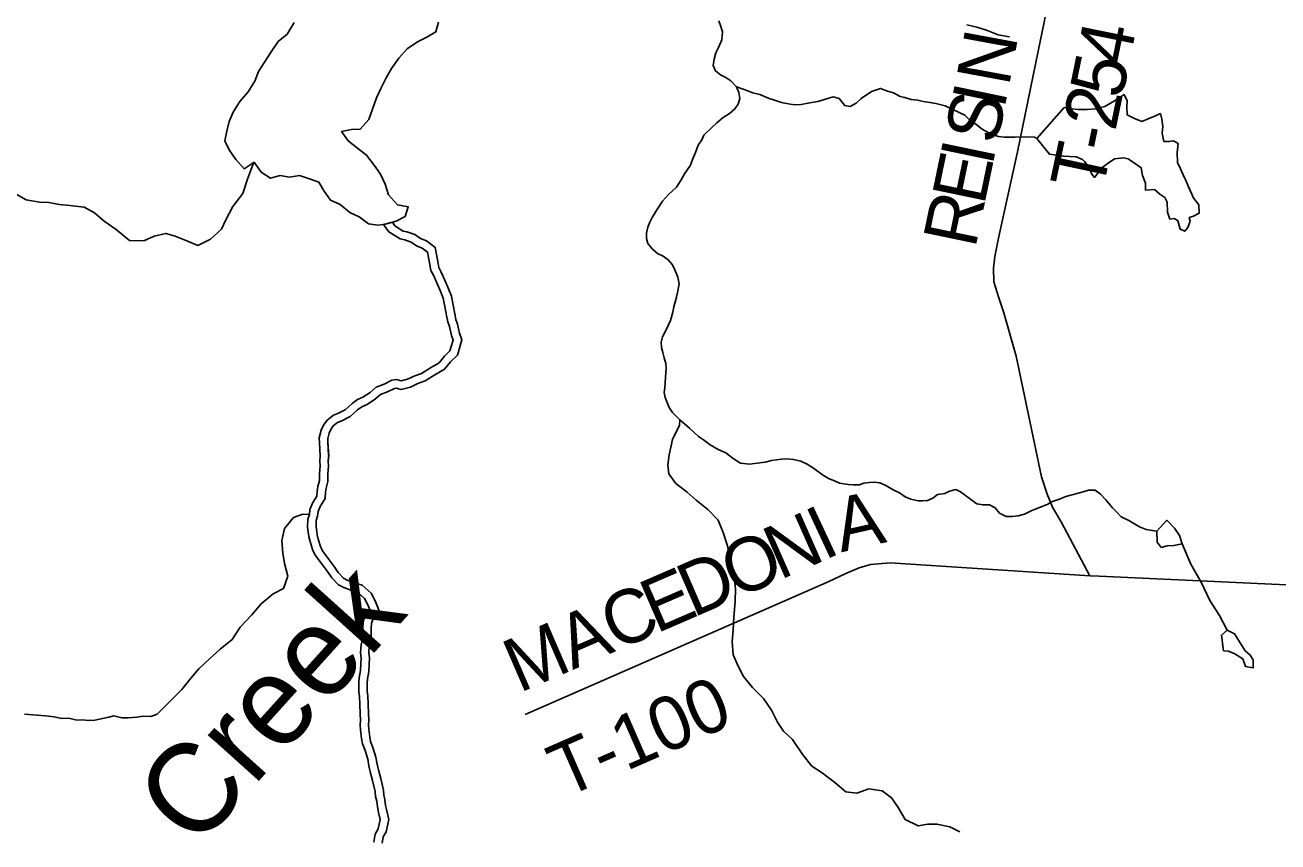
# Model space of a CAD drawing. Extents: x 1310247 to 1664935, y 235267 to 584339.
# Drawn here: x 1510976 to 1517993, y 362419 to 366994 of the extents above; entities that cross this region are included whole.
import ezdxf

# ---------------------------------------------------------------- set-up
doc = ezdxf.new("R2010")
doc.units = 0
for name, color, linetype in [('GM_X_Major_Lake', 7, 'Continuous'), ('GM_X_Minor_Lake', 7, 'Continuous'), ('GM_X_Minor_River', 7, 'Continuous'), ('GM_X_Minor_River_Text', 7, 'Continuous'), ('GM_X_Township_Road', 7, 'Continuous'), ('GM_X_Township_Road_Text', 7, 'Continuous')]:
    doc.layers.add(name, color=color, linetype=linetype)

msp = doc.modelspace()

# ---------------------------------------------------------------- linework, layer by layer
at = {"layer": 'GM_X_Major_Lake'}
for points in [[(1512483.3, 367008.6), (1512444, 366943.1), (1512393.1, 366901.9), (1512353.9, 366844.4), (1512316.8, 366786.8), (1512283.7, 366733.2), (1512262.6, 366679.4), (1512225.4, 366619.9), (1512178.3, 366566.5), (1512141.1, 366507), (1512118.1, 366453.2), (1512105.1, 366399.2), (1512094, 366345.2), (1512119.2, 366294.6), (1512156.3, 366241.7), (1512203.4, 366188.6), (1512258.2, 366225.7), (1512297.3, 366170.8), (1512350.9, 366137.6), (1512405.2, 366150.7), (1512457.2, 366141.7), (1512513.5, 366150.7), (1512569.4, 366133.6), (1512621.1, 366114.5), (1512650.3, 366063.8), (1512685.4, 366012.9), (1512741.1, 365989.8), (1512794.5, 365944.6), (1512846.1, 365919.6), (1512899.5, 365880.4), (1512951.6, 365873.4), (1512983.3, 365877.9)], [(1513034.1, 365889.8), (1513054.2, 365895.6), (1513104.9, 365922.8), (1513121.9, 365976.7), (1513061.9, 365987.8), (1513010.8, 366043), (1512991.9, 366103.6), (1512966.8, 366158.3), (1512931.7, 366209.1), (1512888.6, 366266.1), (1512837.2, 366305.3), (1512785.8, 366346.4), (1512748.7, 366397.3), (1512803, 366408.3), (1512853.2, 366411.4), (1512900.3, 366464.7), (1512921.5, 366522.5), (1512944.7, 366586.4), (1512967.7, 366638.1), (1512998.9, 366697.8), (1513027.9, 366751.5), (1513069.1, 366808.9), (1513116.2, 366860.2), (1513173.1, 366899.3), (1513225.7, 366926.5), (1513276.4, 366955.6), (1513291.4, 367009.6)], [(1512983.3, 365877.9), (1513001.8, 365880.5), (1513034.1, 365889.8)]]:
    msp.add_lwpolyline(points, dxfattribs=at)
at = {"layer": 'GM_X_Minor_Lake'}
for points in [[(1517266.2, 366469.5), (1517229.9, 366454.1), (1517190, 366470.8), (1517148.2, 366491.6), (1517146.9, 366533.8), (1517147.5, 366569.9), (1517132, 366604.3), (1517087.4, 366574.9), (1517022.6, 366537.9), (1516970.2, 366524.7), (1516924, 366521.4), (1516873.9, 366520.3), (1516833.8, 366525), (1516795.8, 366531.6), (1516641.7, 366359.2)], [(1516641.7, 366359.2), (1516713.2, 366272), (1516791.3, 366260.6), (1516863.4, 366255.4), (1516897.3, 366240.8), (1516909.1, 366230.5), (1516934.6, 366196), (1516950.1, 366159.5), (1516965.8, 366141.2), (1516984.3, 366165), (1517008.9, 366196.7), (1517041.4, 366220.3), (1517077.9, 366245.8), (1517128.2, 366250.9), (1517154.1, 366244.5), (1517195.8, 366217.7), (1517227.5, 366195), (1517234.8, 366150.8), (1517250.2, 366108.3), (1517251.5, 366070.1), (1517301.7, 366073.3), (1517331.4, 366046.7), (1517359.2, 366028.2), (1517372.8, 366001.8), (1517373.8, 365945.6), (1517387.2, 365907.2), (1517413.4, 365910.8), (1517431.2, 365898.5), (1517444.5, 365852), (1517470.4, 365839.6), (1517488.8, 365861.3), (1517501.4, 365895.3), (1517495.7, 365915.5), (1517519.9, 365923.1), (1517552.3, 365940.6), (1517549.1, 365986.8), (1517517.6, 366027.5), (1517510, 366047.8), (1517492.6, 366088.2), (1517479.1, 366120.5), (1517461.6, 366155), (1517446.1, 366189.4), (1517430.6, 366223.8), (1517427.6, 366280.1), (1517434.4, 366330.2), (1517408.6, 366346.6), (1517382.4, 366341.1), (1517354.4, 366341.5), (1517345.1, 366387.9), (1517347.7, 366426), (1517342.4, 366466.2), (1517334.9, 366498.5), (1517306.6, 366484.9), (1517266.2, 366469.5)], [(1517314.6, 364159.8), (1517371.1, 364220.6), (1517412.5, 364175.8), (1517441.9, 364135.1), (1517457.2, 364088.7), (1517408.9, 364079.5), (1517372.8, 364078), (1517338.5, 364068.6)], [(1517338.5, 364068.6), (1517316.9, 364099.1), (1517314.6, 364159.8)], [(1517707.9, 363604.5), (1517749.7, 363585.8), (1517781, 363535), (1517808.3, 363490.4), (1517838, 363465.8), (1517853.6, 363439.4), (1517854.9, 363395.2), (1517810.8, 363402), (1517795.5, 363444.4), (1517751.8, 363473.3), (1517716, 363487.9), (1517687.9, 363490.4), (1517677.4, 363576.9)], [(1517677.4, 363576.9), (1517707.9, 363604.5)]]:
    msp.add_lwpolyline(points, dxfattribs=at)
at = {"layer": 'GM_X_Minor_River'}
msp.add_line((1513034.1, 365889.8), (1512983.3, 365877.9), dxfattribs=at)
for points in [[(1514861.7, 367017.6), (1514873, 366985.3), (1514882.4, 366957), (1514877.4, 366911), (1514858.5, 366869.2), (1514843.9, 366839.5), (1514835.1, 366803.5), (1514830.4, 366767.5), (1514841.7, 366737.2), (1514871.3, 366714.5), (1514901, 366699.9), (1514928.6, 366681.2), (1514959.9, 366648.5), (1514973.3, 366616.1), (1514978.6, 366581.9), (1514969.9, 366552), (1514951.3, 366524.3), (1514920.8, 366498.9), (1514886.3, 366475.5), (1514849.6, 366446.2), (1514823.1, 366422.7), (1514778.1, 366377.5), (1514765.6, 366351.7), (1514744.9, 366322), (1514730, 366280.2), (1514713.2, 366240.4), (1514702.5, 366208.6), (1514669.5, 366161.1), (1514650.8, 366127.4), (1514623.9, 366085.8), (1514579, 366044.7), (1514546.2, 366007.2), (1514517.3, 365965.7), (1514488.2, 365916.2), (1514475.6, 365890.4), (1514463, 365862.5), (1514456.3, 365828.6), (1514455.7, 365798.5), (1514463.1, 365770.3), (1514488.5, 365741.7), (1514518, 365715), (1514549.7, 365700.3), (1514577.3, 365679.6), (1514602.7, 365651), (1514614.1, 365622.7), (1514631.2, 365582.2), (1514638.4, 365544), (1514631.6, 365506), (1514624.9, 365470), (1514609.7, 365416.2), (1514603.1, 365386.2), (1514590.1, 365340.4), (1514579.6, 365314.5), (1514567, 365286.7), (1514546.2, 365249), (1514537.5, 365219.1), (1514540.9, 365189), (1514548.3, 365160.7), (1514555.7, 365130.5), (1514565, 365098.2), (1514566.5, 365072.1), (1514563.4, 365022), (1514560.7, 364990), (1514558.2, 364963.9), (1514555.6, 364935.9)], [(1516249.8, 366994.6), (1516305.8, 366981.6), (1516359.7, 366964.6), (1516425.5, 366939.5), (1516489.5, 366928.3)], [(1514959.9, 366648.5), (1515003.7, 366633.5), (1515051.3, 366614.5), (1515091.1, 366605.6), (1515142.7, 366582.5), (1515172.5, 366573.8), (1515212.3, 366561), (1515260.1, 366552), (1515288, 366547.4), (1515322.1, 366548.7), (1515360.3, 366555.9), (1515416.5, 366566.7), (1515501.1, 366593), (1515534.9, 366582.3), (1515566.1, 366543.5), (1515596.1, 366538.9), (1515630.4, 366556.2), (1515659, 366583.7), (1515715.9, 366622.7), (1515766.3, 366639.7), (1515806, 366624.8), (1515839.8, 366614.1), (1515877.4, 366593.2), (1515903.3, 366588.7), (1515939.1, 366577.9), (1515975, 366573.1), (1516004.9, 366566.5), (1516044.8, 366559.6), (1516076.7, 366555), (1516128.5, 366541.8), (1516168.1, 366523), (1516239.4, 366489.4), (1516268.8, 366458.7), (1516300.4, 366440), (1516335.9, 366411.1), (1516383.3, 366384.1), (1516427, 366369.1), (1516459, 366366.4), (1516493, 366365.7), (1516519, 366367.2), (1516581.1, 366367.9), (1516629.1, 366366.9), (1516641.7, 366359.2)], [(1512258.2, 366225.7), (1512247.6, 366202.2), (1512222.3, 366130.4), (1512194.8, 366050.6), (1512139.4, 365977.3), (1512100, 365903.7), (1512075, 365851.9), (1512013.8, 365794.8), (1511943, 365759.9), (1511881.3, 365785.1), (1511815.7, 365812.4), (1511763.8, 365827.4), (1511699.4, 365812.5), (1511640.8, 365785.4), (1511560.6, 365786.8), (1511485.5, 365848.4), (1511418.2, 365895.8), (1511364.9, 365942.9), (1511307.3, 365974.1), (1511227.2, 365983.5), (1511169.2, 365988.6), (1511109.2, 365999.7), (1511057.2, 366002.6), (1510981.2, 366016.1), (1510925.6, 366047.2)], [(1512983.3, 365877.9), (1513012.9, 365835.6), (1513042.4, 365816.9), (1513075.9, 365796.1), (1513101.8, 365791.5), (1513137.5, 365778.7), (1513168.9, 365758), (1513200.6, 365745.2), (1513230.1, 365722.5), (1513240.7, 365662.1), (1513247.7, 365619.8), (1513263.1, 365593.4), (1513274.5, 365567.1), (1513301.2, 365508.3), (1513318.1, 365463.8), (1513327.1, 365417.5), (1513335.9, 365367.1), (1513343.2, 365332.9), (1513352.6, 365306.6), (1513363.4, 365256.2), (1513372.8, 365229.9), (1513355.5, 365170.1), (1513324.9, 365140.7), (1513294.1, 365103.3), (1513245.5, 365074.3), (1513196.9, 365043.3), (1513158.6, 365030.1), (1513118.2, 365010.9), (1513082.1, 365001.7), (1513056.3, 365008.3), (1513030.2, 365004.8), (1512987.8, 364983.7), (1512941.5, 364966.7), (1512908.9, 364937.3), (1512868.3, 364910.2), (1512838.1, 364896.8), (1512807.6, 364875.4), (1512768.9, 364840.2), (1512730.5, 364820.9), (1512702.3, 364809.5), (1512667.7, 364782.2), (1512647.1, 364752.6), (1512634.5, 364724.8), (1512623.5, 364682.9), (1512624.9, 364654.8), (1512629.3, 364582.5)], [(1512676.2, 364581.8), (1512671.6, 364657.4), (1512670.6, 364678), (1512678.7, 364709.1), (1512687.9, 364729.4), (1512702.1, 364749.8), (1512726, 364768.7), (1512749.7, 364778.3), (1512795.6, 364801.2), (1512836.9, 364838.8), (1512861.2, 364855.9), (1512890.9, 364869), (1512937.7, 364900.3), (1512966.1, 364925.9), (1513006.3, 364940.7), (1513044.1, 364959.5), (1513053.4, 364960.7), (1513082.1, 364953.4), (1513134.2, 364966.7), (1513176.3, 364986.7), (1513217.3, 365000.9), (1513270.1, 365034.5), (1513325, 365067.3), (1513359.2, 365108.9), (1513396.9, 365145.1), (1513421.9, 365231.5), (1513408.5, 365269.1), (1513397.6, 365319.5), (1513388.3, 365345.6), (1513381.9, 365376), (1513373.1, 365426), (1513363.3, 365476.7), (1513344.3, 365526.3), (1513317.3, 365586), (1513304.9, 365614.5), (1513292.4, 365636), (1513286.8, 365670), (1513273, 365748.5), (1513224.1, 365786.2), (1513190.7, 365799.6), (1513158.5, 365820.8), (1513113.9, 365836.9), (1513092.9, 365840.6), (1513067.3, 365856.5), (1513046.1, 365869.9), (1513034.1, 365889.8)], [(1513034.1, 365889.8), (1513046.1, 365869.9), (1513067.3, 365856.5), (1513092.9, 365840.6), (1513113.9, 365836.9), (1513158.5, 365820.8), (1513190.7, 365799.6), (1513224.1, 365786.2), (1513273, 365748.5), (1513286.8, 365670), (1513292.4, 365636), (1513304.9, 365614.5), (1513317.3, 365586), (1513344.3, 365526.3), (1513363.3, 365476.7), (1513373.1, 365426), (1513381.9, 365376), (1513388.3, 365345.6), (1513397.6, 365319.5), (1513408.5, 365269.1), (1513421.9, 365231.5), (1513396.9, 365145.1), (1513359.2, 365108.9), (1513325, 365067.3), (1513270.1, 365034.5), (1513217.3, 365000.9), (1513176.3, 364986.7), (1513134.2, 364966.7), (1513082.1, 364953.4), (1513053.4, 364960.7), (1513044.1, 364959.5), (1513006.3, 364940.7), (1512966.1, 364925.9), (1512937.7, 364900.3), (1512890.9, 364869), (1512861.2, 364855.9), (1512836.9, 364838.8), (1512795.6, 364801.2), (1512749.7, 364778.3), (1512726, 364768.7), (1512702.1, 364749.8), (1512687.9, 364729.4), (1512678.7, 364709.1), (1512670.6, 364678), (1512671.6, 364657.4), (1512676, 364585.3)], [(1514555.6, 364935.9), (1514561, 364907.7), (1514583.8, 364853.1), (1514601.2, 364824.6), (1514642.4, 364783.7), (1514697.5, 364736.4), (1514746.5, 364689.2), (1514776.1, 364670.5), (1514813.6, 364643.7), (1514857, 364616.7), (1514900.7, 364597.7), (1514942, 364566.8), (1514983.5, 364539.8), (1515033.4, 364534.8), (1515061.5, 364538.2), (1515121.7, 364547), (1515156, 364556.3), (1515212.1, 364563.1), (1515246.2, 364564.4), (1515278.2, 364561.8), (1515320, 364550.9), (1515355.6, 364534.1), (1515391.2, 364513.3), (1515442.5, 364476.1), (1515476, 364455.3), (1515509.8, 364442.6), (1515537.5, 364428), (1515585.4, 364421), (1515613.3, 364418.4), (1515647.4, 364419.7), (1515673.6, 364429.1), (1515705.7, 364432.5), (1515731.8, 364433.9), (1515763.7, 364431.3), (1515793.4, 364416.6), (1515840.9, 364389.5), (1515872.6, 364374.8), (1515904.1, 364352.1), (1515935.9, 364339.4), (1515977.7, 364330.5), (1516003.8, 364330), (1516029.8, 364331.4), (1516060.1, 364344.8), (1516086.5, 364364.3), (1516126.7, 364371.5), (1516153, 364383), (1516189.2, 364392.3), (1516214.9, 364379.7), (1516242.5, 364359.1), (1516272.1, 364336.4), (1516305.6, 364313.6), (1516341.5, 364306.9), (1516377.5, 364308.1), (1516409.2, 364291.4), (1516432.6, 364260.8), (1516470.2, 364242), (1516504.2, 364241.3), (1516538.3, 364246.6), (1516572.6, 364255.9), (1516615, 364275.1), (1516699.8, 364309.4), (1516730.2, 364326.8), (1516768.4, 364338.1), (1516804.8, 364353.4), (1516901.4, 364379.4), (1516931.6, 364388.8), (1516969.6, 364390), (1516999.2, 364367.3), (1517028.5, 364334.6), (1517065.6, 364289.7), (1517091.1, 364267.1), (1517114.6, 364240.6), (1517158.2, 364219.6), (1517217.5, 364184.3), (1517255.2, 364169.5), (1517313, 364160.2), (1517314.6, 364159.8)], [(1514642.4, 364783.7), (1514641.6, 364754.3), (1514602.1, 364672.7), (1514582.7, 364586.6), (1514575.7, 364530.5), (1514580.9, 364480.2), (1514620.1, 364427.4), (1514683.5, 364378.1), (1514734.9, 364333.1), (1514800.2, 364281.8), (1514857.4, 364220.6), (1514886.3, 364151.8), (1514909.2, 364077.1), (1514920.3, 364020.7), (1514927.5, 363970.4), (1514944.5, 363909.8), (1514955.4, 363839.4), (1514952.1, 363765.1), (1514944.7, 363678.9), (1514941.5, 363606.7), (1514936.4, 363542.5), (1514941.1, 363468.1), (1514972.1, 363399.3), (1514999.3, 363346.6), (1515050.4, 363283.5), (1515111.6, 363222.3), (1515156.6, 363157.3), (1515189.6, 363090.4), (1515222.9, 363039.7), (1515274.3, 362992.6), (1515331, 362907.3), (1515382.1, 362844.2), (1515439.7, 362807.1), (1515511, 362751.7), (1515572.3, 362700.5), (1515634.4, 362693.4), (1515701, 362716.4), (1515777, 362705.1), (1515828.5, 362666.1), (1515865.8, 362613.2), (1515904.7, 362544.3), (1515978.4, 362508.9), (1516032.7, 362518.1), (1516082.9, 362519.2), (1516154.8, 362504), (1516210.5, 362476.9)], [(1512629.3, 364582.5), (1512626.6, 364552.5), (1512628, 364526.4), (1512625, 364482.3), (1512624.2, 364444.2), (1512615.4, 364410.3), (1512610.8, 364382.3), (1512610.2, 364356.3), (1512587.5, 364320.7), (1512570.6, 364280.9), (1512568, 364252.9), (1512559.4, 364227), (1512558.4, 364182.9), (1512565.2, 364130.6), (1512572.6, 364102.4), (1512585.6, 364058), (1512600.8, 364025.5), (1512635.7, 363978.6), (1512668.7, 363933.8), (1512693.9, 363899.1), (1512730.9, 363860.2), (1512760.5, 363843.5), (1512800.1, 363828.5), (1512839.8, 363815.6), (1512877, 363782.7), (1512894.2, 363750.2), (1512909.4, 363711.8), (1512883.1, 363698.3), (1512870.1, 363652.5), (1512867.3, 363616.5), (1512868.1, 363564.3), (1512857.2, 363522.4), (1512854.2, 363480.3), (1512857.5, 363446.2), (1512856.8, 363418.1), (1512854, 363380.1), (1512847.1, 363338.1), (1512844.4, 363310.1), (1512845.3, 363259.9), (1512848.7, 363233.8), (1512849.7, 363189.6), (1512852.5, 363137.4), (1512853.7, 363101.3), (1512853.1, 363073.2), (1512854.5, 363047.1), (1512859.4, 362998.8), (1512864.7, 362968.6), (1512879.9, 362932.2), (1512894.8, 362883.7), (1512901.9, 362845.5), (1512911, 362805.1), (1512922, 362762.8), (1512936.7, 362702.3), (1512938, 362674.2), (1512945.4, 362647.9), (1512948.7, 362615.8), (1512956, 362583.5), (1512965.1, 362545.2), (1512953.9, 362493.3), (1512937.3, 362463.6), (1512928.3, 362417.6)], [(1512974.9, 362412.6), (1512981.7, 362447.2), (1512998.2, 362476.6), (1513013, 362545.7), (1513001.5, 362594.1), (1512994.9, 362623.3), (1512991.5, 362656.7), (1512984.5, 362681.8), (1512983.1, 362709), (1512967.4, 362774.2), (1512956.4, 362816.2), (1512947.7, 362854.9), (1512940.3, 362894.9), (1512923.9, 362948.1), (1512909.9, 362981.8), (1512905.8, 363005.3), (1512901.1, 363050.7), (1512899.9, 363074), (1512900.5, 363101.5), (1512899.3, 363139.4), (1512896.4, 363191.4), (1512895.4, 363237.3), (1512892, 363263.3), (1512891.2, 363308.3), (1512893.5, 363332.1), (1512900.5, 363374.5), (1512903.5, 363415.8), (1512904.3, 363447.8), (1512901.1, 363480.9), (1512903.5, 363514.8), (1512914.9, 363558.6), (1512914, 363615), (1512916.3, 363644.2), (1512922.5, 363666), (1512968.4, 363689.5), (1512936.8, 363769.8), (1512914.3, 363812.1), (1512863.5, 363857.1), (1512815.6, 363872.7), (1512780.4, 363886), (1512760, 363897.5), (1512729.8, 363929.1), (1512706.4, 363961.4), (1512673.3, 364006.4), (1512641.1, 364049.7), (1512629.4, 364074.6), (1512617.6, 364114.8), (1512611.2, 364139.6), (1512605.2, 364185.4), (1512606, 364219), (1512614, 364243.2), (1512616.5, 364269.3), (1512629, 364298.8), (1512656.7, 364342.1), (1512657.5, 364378), (1512661.2, 364400.6), (1512670.8, 364437.8), (1512671.8, 364480.2), (1512674.9, 364526), (1512673.5, 364551.7), (1512676.2, 364581.8)], [(1512675.9, 364578.4), (1512673.5, 364551.7), (1512674.9, 364526), (1512671.8, 364480.2), (1512670.8, 364437.8), (1512661.2, 364400.6), (1512657.5, 364378), (1512656.7, 364342.1), (1512629, 364298.8), (1512616.5, 364269.3), (1512614, 364243.2), (1512606, 364219), (1512605.2, 364185.4), (1512611.2, 364139.6), (1512617.6, 364114.8), (1512629.4, 364074.6), (1512641.1, 364049.7), (1512673.3, 364006.4), (1512706.4, 363961.4), (1512729.8, 363929.1), (1512760, 363897.5), (1512780.4, 363886), (1512815.6, 363872.7), (1512863.5, 363857.1), (1512914.3, 363812.1), (1512936.8, 363769.8), (1512968.4, 363689.5), (1512922.5, 363666), (1512916.3, 363644.2), (1512914, 363615), (1512914.9, 363558.6), (1512903.5, 363514.8), (1512901.1, 363480.9), (1512904.3, 363447.8), (1512903.5, 363415.8), (1512900.5, 363374.5), (1512893.5, 363332.1), (1512891.2, 363308.3), (1512892, 363263.3), (1512895.4, 363237.3), (1512896.4, 363191.4), (1512899.3, 363139.4), (1512900.5, 363101.5), (1512899.9, 363074), (1512901.1, 363050.7), (1512905.8, 363005.3), (1512909.9, 362981.8), (1512923.9, 362948.1), (1512940.3, 362894.9), (1512947.7, 362854.9), (1512956.4, 362816.2), (1512967.4, 362774.2), (1512983.1, 362709), (1512984.5, 362681.8), (1512991.5, 362656.7), (1512994.9, 362623.3), (1513001.5, 362594.1), (1513013, 362545.7), (1512998.2, 362476.6), (1512981.7, 362447.2), (1512974.9, 362412.6)], [(1512568, 364252.9), (1512530.8, 364255.5), (1512478.4, 364236.3), (1512429.2, 364174.9), (1512414, 364106.9), (1512418.9, 364036.5), (1512427.9, 363978.1), (1512446.8, 363907.5), (1512423.6, 363839.6), (1512364.9, 363808.5), (1512297.8, 363753.4), (1512246.6, 363692), (1512181.2, 363622.8), (1512135.9, 363553.2), (1512068.8, 363498.1), (1512007.8, 363444.9), (1511948.6, 363389.7), (1511905.7, 363338.2), (1511854.4, 363272.8), (1511716.4, 363135.1)], [(1517457.2, 364088.7), (1517505.4, 363975.4), (1517563.9, 363870), (1517610.4, 363770.8), (1517665.2, 363687.6), (1517707.9, 363604.5)], [(1511716.4, 363135.1), (1511679.8, 363121.3), (1511635.9, 363124.2), (1511601.8, 363119), (1511553.8, 363114), (1511517.8, 363114.8), (1511472.2, 363125.9), (1511444, 363118.5), (1511365.8, 363102.1), (1511335.7, 363098.8), (1511291.9, 363103.8), (1511265.9, 363102.3), (1511220.2, 363113.4), (1511180.2, 363110.3), (1511138.5, 363119.2), (1511090.7, 363126.3), (1510972.3, 363135)]]:
    msp.add_lwpolyline(points, dxfattribs=at)
at = {"layer": 'GM_X_Township_Road'}
for points in [[(1516939, 363910.6), (1516779.7, 364207.7), (1516730.1, 364294.7), (1516700.7, 364367), (1516668.6, 364464.7), (1516526.7, 365139.4), (1516458.4, 365381.7), (1516430.3, 365466), (1516402.2, 365557), (1516399.5, 365633.3), (1516406.2, 365697.6), (1516429, 365810), (1516533.4, 366283.8), (1516649.8, 366847.4), (1516683.3, 367010.7), (1516694, 367069.6), (1516712.7, 367135.2), (1516723.4, 367214.1), (1516718.1, 367273), (1516714.1, 367287.4)], [(1513776.9, 363133.4), (1515474.1, 363875.5), (1515572.2, 363922.2), (1515648.1, 363953.7), (1515711.2, 363973.6), (1515821, 363981.8), (1516939, 363910.6), (1516991.2, 363908.2)], [(1516991.2, 363908.2), (1519290.1, 363801)]]:
    msp.add_lwpolyline(points, dxfattribs=at)

# ---------------------------------------------------------------- texts
at = {"layer": 'GM_X_Minor_River_Text'}
msp.add_text('Creek', height=500.08, rotation=48.00906, dxfattribs=at).set_placement((1511931.1, 362367.7))
at = {"layer": 'GM_X_Township_Road_Text'}
for s, rotation, p in [('N', 79.50101, (1516485.8, 366645.1)), ('4', 78.53943, (1517155.7, 366754.9)), ('5', 78.34576, (1517118.4, 366574.3)), ('I', 78.24462, (1516459.3, 366517.5)), ('S', 78.23859, (1516418.1, 366319.3)), ('2', 78.32079, (1517081.3, 366394.6)), ('-', 78.29294, (1517056.5, 366274.9)), ('I', 78.23998, (1516393, 366198.7)), ('T', 77.92876, (1517009.2, 366053.8)), ('E', 78.24282, (1516347.2, 365979)), ('R', 78.23998, (1516297, 365737.8)), ('A', 12.62778, (1515546, 364040.8)), ('I', 25.04117, (1515450.6, 363994.2)), ('N', 23.7953, (1515202.5, 363884.7)), ('O', 23.43315, (1514958.4, 363778.9)), ('D', 23.4344, (1514716.2, 363673.9)), ('E', 23.43184, (1514510.3, 363584.7)), ('C', 23.43452, (1514284.2, 363486.7)), ('A', 23.43081, (1514041.9, 363381.7)), ('M', 23.43303, (1513743.2, 363252.2)), ('T-100', 23.67724, (1513994.8, 362662.6))]:
    msp.add_text(s, height=300, rotation=rotation, dxfattribs=at).set_placement(p)

doc.saveas('drawing.dxf')
